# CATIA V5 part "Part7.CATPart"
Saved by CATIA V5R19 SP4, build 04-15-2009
Part number: Socle
Bounding box of the stored display mesh (mm): x -350 to 350, y -310.777 to 500, z -325 to -225
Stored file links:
  G:\EU_thinkMotion\CFAO_2010\MMS_groupe1\MMS_groupe1\OK\ppiault\piault\piault_cfao\Part7.CATPart
  G:\EU_thinkMotion\CFAO_2010\MMS_groupe1\MMS_groupe1\OK\ppiault\piault\piault_cfao\Part2.CATPart
  G:\EU_thinkMotion\CFAO_2010\MMS_groupe1\MMS_groupe1\OK\ppiault\piault\piault_cfao\Part6.CATPart
  D:\Catia\Finaltest.CATProduct
  G:\Catia Projet\CFAO2\Product2.CATProduct
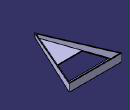
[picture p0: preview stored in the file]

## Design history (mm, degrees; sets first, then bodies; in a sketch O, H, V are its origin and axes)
Parameters
  z0 = 0 mm
  y0 = 0 mm
  z0p = 0 mm
  y0p = -280 mm
  z0s = -250 mm
  y0s = -286 mm
  z0t = -300 mm
  y0t = 500 mm
  epaisseur_tole = 10 mm
External parameters (linked from other documents)
  External.DiametreRabatteur = 400 mm
  External.bas_axe = 255 mm
Set1
  Point1: (0, 0 {= y0}, 0 {= z0})
  Point2: (0, -280 {= y0p}, 0 {= z0p})
  Point3: (0, -286 {= y0s}, -250 {= z0s})
  Point4: (0, 500 {= y0t}, -300 {= z0t})
Body1 (main body)
  Sketch1 on yz-plane, origin (0, 0, 0), H (0, 1, 0), V (0, 0, 1)
    line L1 (-286, -275) -> (500, -325)
    point P1 (-286, -275)
    point P2 (500, -325)
    line L2 (-286, -275) -> (-310.7769, -225)
    line L3 (-310.7769, -225) -> (500, -225)
    line L4 (500, -325) -> (500, -225)
    length L4 = 100
    distance H P1 = 275 {= External.bas_axe +20mm}
    distance V P1 = 286 {= 0.715*External.DiametreRabatteur}
    distance P2 V = 500 {= External.DiametreRabatteur  +100mm}
    distance P2 H = 325 {= External.bas_axe +70mm}
    angle L2 L1 = 120
    vertical: L4 V
    horizontal: L3 H
  Pad1: profile Sketch1, direction (1, 0, 0), length 350, mirrored extent
  Sketch2 on face of Pad1 from Sketch1.L3, origin (0, 6.7002, -225), H (1, 0, 0), V (0, 1, 0)
    line L1 (-350, 493.2998) -> (350, 493.2998)
    point P1 (-350, 493.2998)
    point P2 (350, 493.2998)
    line L2 (350, 493.2998) -> (0, -317.477)
    point P3 (0, -317.477)
    line L3 (-350, 493.2998) -> (0, -317.477)
    point P4 (0, -317.477)
    reference projected point E1 (-350, 493.2998) from vertex [face of Pad1 from Sketch1.L3 | start face of Pad1 | face of Pad1 from Sketch1.L4]
    reference projected point E2 (350, 493.2998) from vertex [face of Pad1 from Sketch1.L3 | end face of Pad1 | face of Pad1 from Sketch1.L4]
    reference projected line E3 (-200, -317.477) -> (200, -317.477) from edge [face of Pad1 from Sketch1.L2 | face of Pad1 from Sketch1.L3]
    reference projected point E4 (350, -317.477) from vertex [face of Pad1 from Sketch1.L2 | end face of Pad1 | face of Pad1 from Sketch1.L3]
    distance E4 P3 = 350
    coincidence: P4 L2, L3 P3, E1 P1, E2 P2, E3 P3
  Pocket1: profile Sketch2, direction (0, 0, -1), length 190, outer side
  Sketch3 on face of Pad1 from Sketch1.L3, origin (0, 6.7002, -225), H (1, 0, 0), V (0, 1, 0)
    line L1 (-334.7912, 483.2998) -> (334.7912, 483.2998)
    line L2 (334.7912, 483.2998) -> (0, -292.2457)
    line L3 (-334.7912, 483.2998) -> (0, -292.2457)
    reference projected line E1 (3.9414, -308.3467) -> (331.3438, 450.0827) from edge [face of Pocket1 from Sketch2.L2 | face of Pad1 from Sketch1.L3]
    reference projected line E2 (-200, 493.2998) -> (200, 493.2998) from edge [face of Pad1 from Sketch1.L3 | face of Pad1 from Sketch1.L4]
    reference projected line E3 (-330.2504, 447.5497) -> (-2.848, -310.8797) from edge [face of Pocket1 from Sketch2.L3 | face of Pad1 from Sketch1.L3]
    distance L2 E1 = 10 {= epaisseur_tole}
    distance E2 L1 = 10 {= epaisseur_tole}
    distance L3 E3 = 10 {= epaisseur_tole}
  Pocket2: profile Sketch3, direction (0, 0, -1), through (limit type 6), offset -10 {= -epaisseur_tole}
  Fillet1: radius 3, on edge [face of Pad1 | face of Pocket1 from Sketch2.L2]; edge [face of Pocket1 from Sketch2.L3 | face of Pad1]
  Sketch4 on face of Pocket2, origin (0, -17.4159, -282.0653), H (-1, 0, 0), V (0, -0.998, 0.0635)
    line L1 (-291.7098, -408.4415) -> (291.7098, -408.4415)
    line L2 (291.7098, -408.4415) -> (184.0063, -158.4415)
    point P3 (184.0063, -158.4415)
    line L3 (-291.7098, -408.4415) -> (-184.0063, -158.4415)
    line L4 (-184.0063, -158.4415) -> (184.0063, -158.4415)
    point P5 (184.0063, -158.4415)
    reference projected line E1 (-3.2732, 261.0739) -> (-335.4937, -510.0722) from edge [face of Pocket2 | face of Pocket2 from Sketch3.L2]
    reference projected line E2 (335.4937, -510.0722) -> (3.2732, 261.0739) from edge [face of Pocket2 | face of Pocket2 from Sketch3.L3]
    reference projected line E3 (334.7213, -508.4415) -> (-334.7213, -508.4415) from edge [face of Pocket2 from Sketch3.L1 | face of Pocket2]
    reference projected line E4 (334.7213, -508.4415) -> (-334.7213, -508.4415) from edge [face of Pocket2 from Sketch3.L1 | face of Pocket2]
    distance E4 L1 = 100
    distance L1 L4 = 250
    coincidence: P5 L2, L4 P3, E1 L3, E2 L2, P3 P5
    parallelism: E3 L1
  Pocket3: profile Sketch4, direction (0, 0.0635, 0.998), through (limit type 6)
